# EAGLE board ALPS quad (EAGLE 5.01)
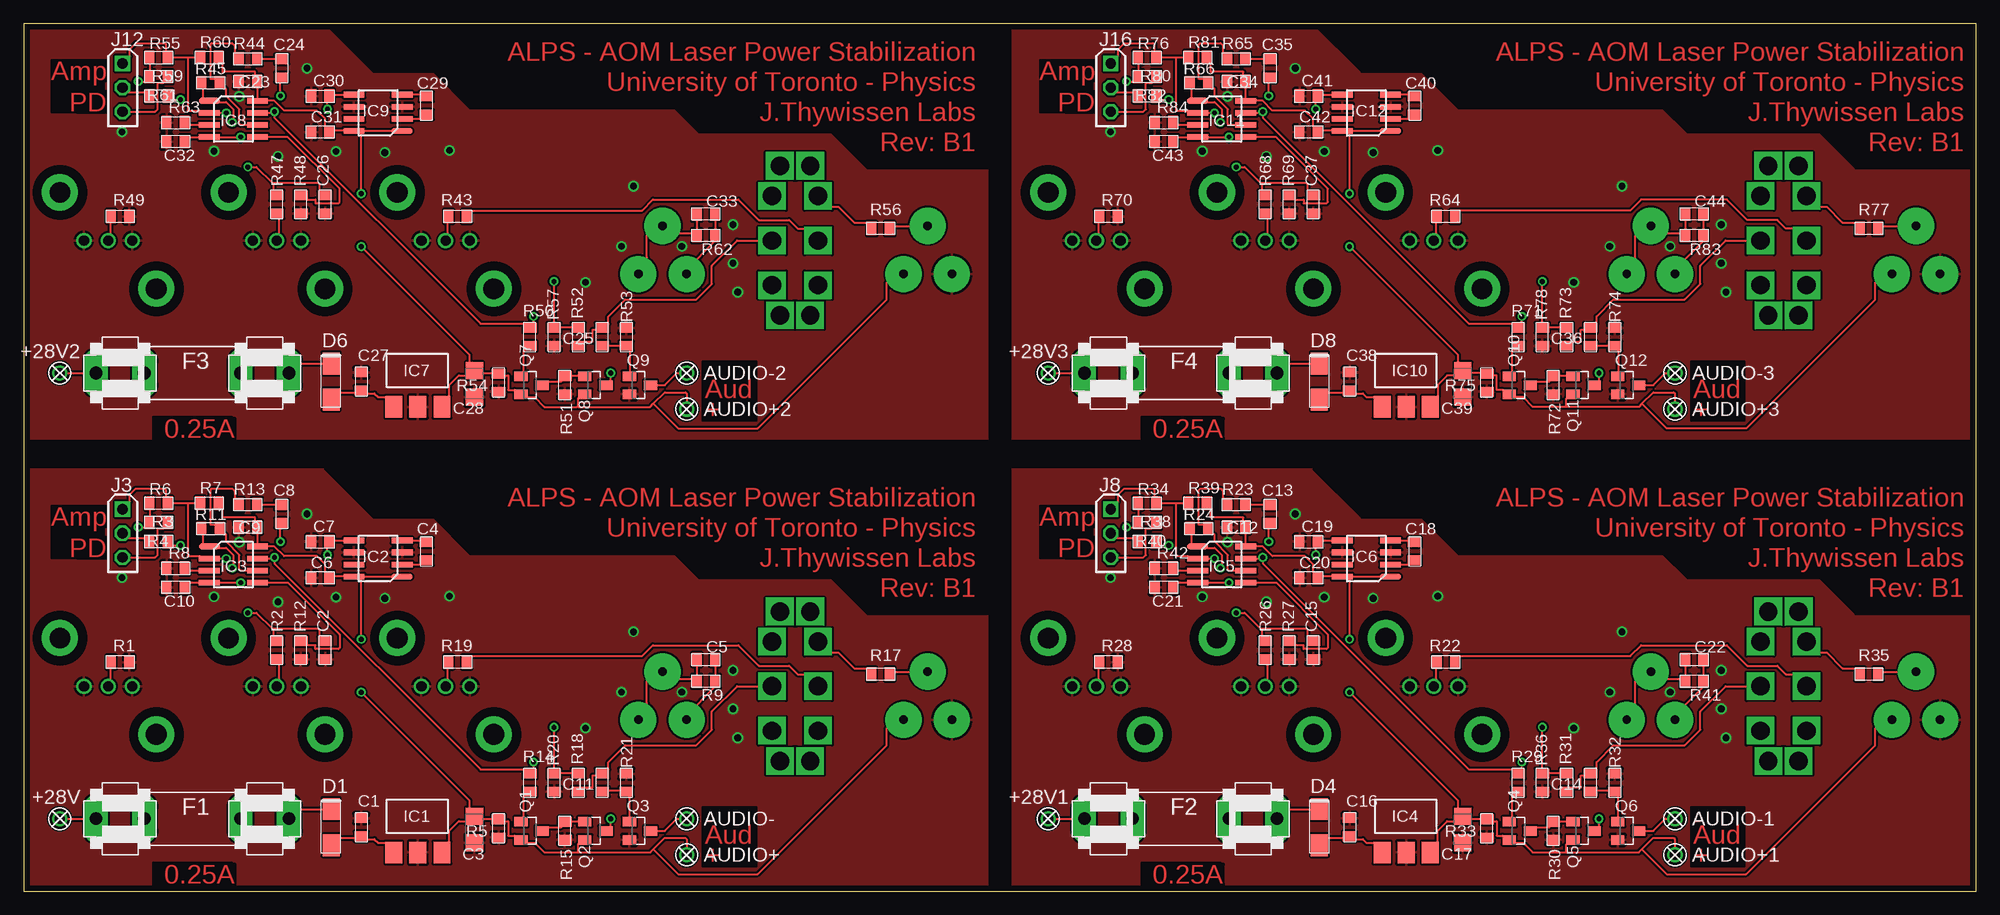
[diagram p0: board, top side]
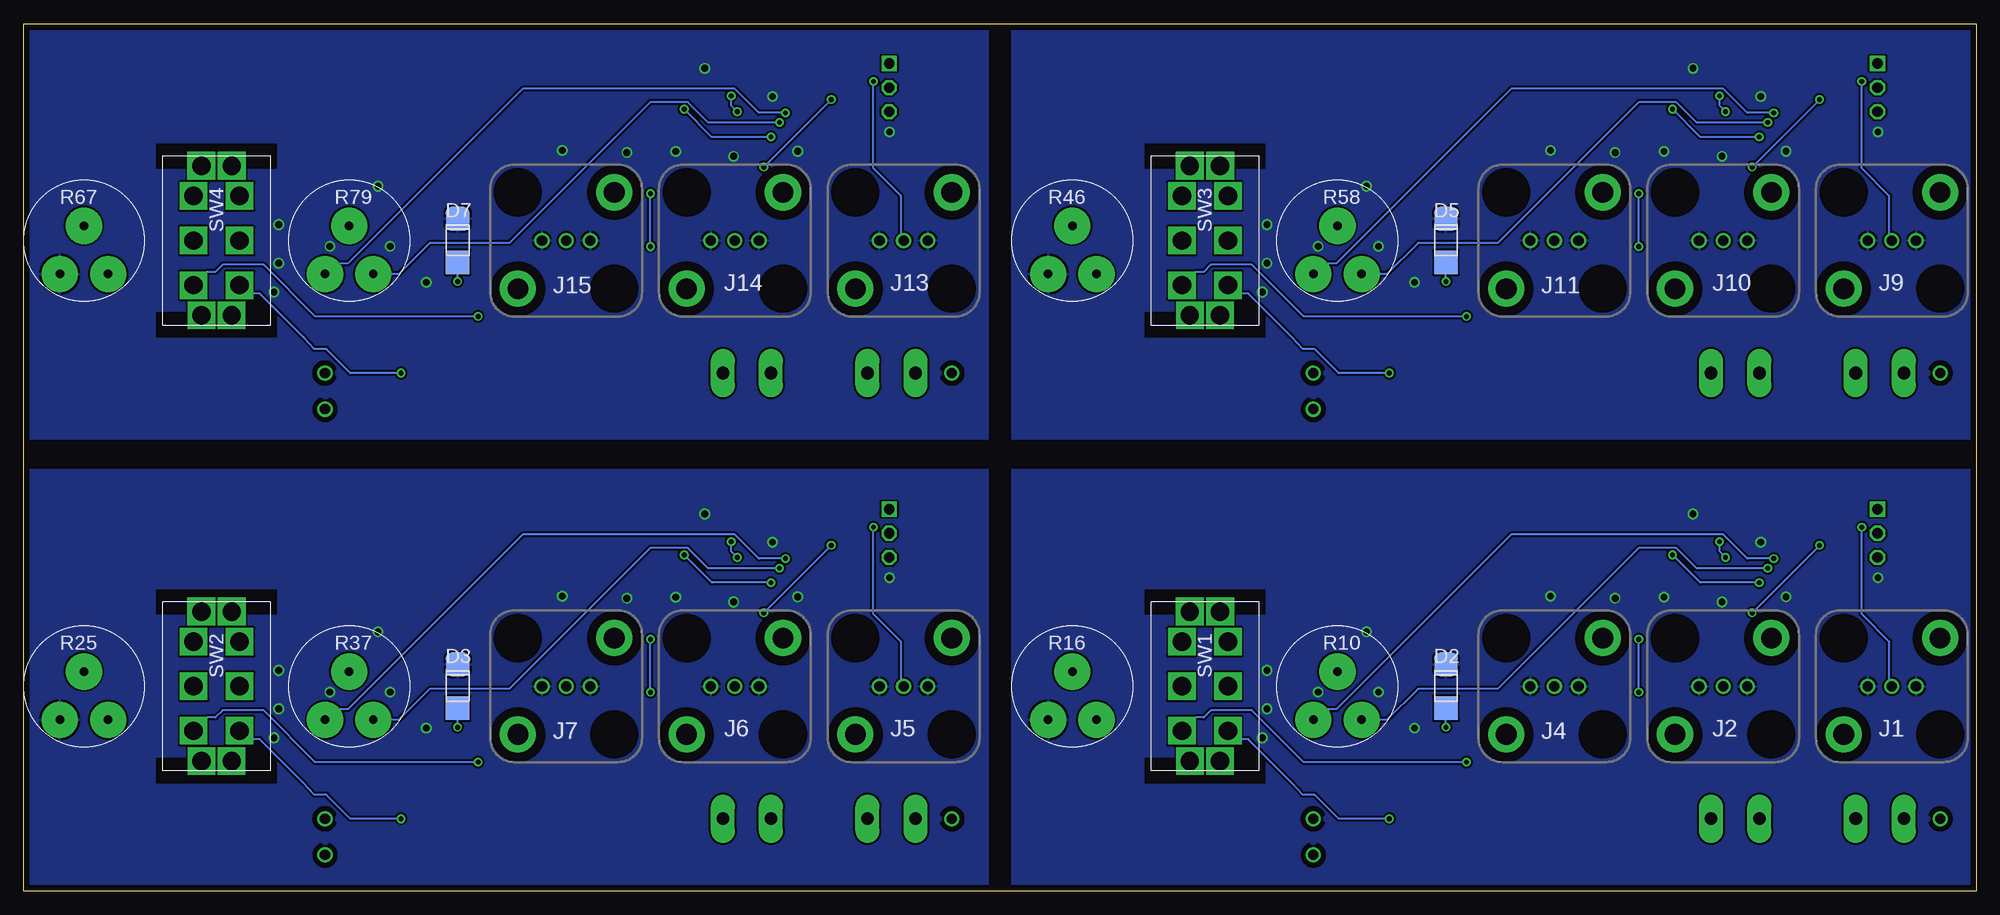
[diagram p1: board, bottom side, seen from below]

Size 205.74 x 91.44 mm. Coordinates in mm from the lower left corner, seen from the top.
Outline: 0,0 205.74,0 205.74,91.44 0,91.44 0,0
Copper layers (1*16): Top 0.035mm / dielectric 1.5mm / Bottom 0.035mm
Design rules "DRC standard check (8mil trace and gap, 20mil drill, etc)": minimum track width 7mil, minimum drill 20mil, track to track 7mil, track to pad 7mil, pad to pad 7mil, via to via 7mil, smd to smd 7mil, copper to edge 25mil, drill to drill 8mil, minimum pad ring 10mil, minimum via ring 8mil, stop-mask expansion 4mil, vias tented up to drill 0mil, thermal gap 10mil
Net classes: 0 default: width 0.203 mm, clearance 0.203 mm
tRestrict: 77 lines
bRestrict: 1 lines

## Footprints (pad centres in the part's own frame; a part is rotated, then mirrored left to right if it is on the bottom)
TP-0.042B = drill 1.067 round: TP 0,0
2012(0805) = smd 1.016 x 1.397: 1 -0.953,0; 2 0.953,0
3216(1206) = smd 1.8 x 1.8: 1 -1.4,0; 2 1.4,0
EIA-A(SMA) = smd 2.3 x 1.8: 1A -1.905,0; 2K 1.905,0
1209 = smd 2.5 x 2.5: A 2.3,0; K -2.3,0
FUSE = drill 1.321 pad 2.54 long: 1A -10.16,0; 1B -5.08,0; 2A 10.16,0; 2B 5.08,0
SOT223 = smd 1.778 x 2.286: 1 -2.54,-2.54; 2@1 0,-2.54; 3 2.54,-2.54
SOIC-8 = smd 0.6 x 2.2: 1 -1.27,-2.54; 2 0,-2.54; 3 1.27,-2.54; 4 2.54,-2.54; 5 2.54,2.54; 6 1.27,2.54; 7 0,2.54; 8 -1.27,2.54
CONN-BNC-AMP-TYPE1VERT = drill 1.067 round: CONDUCTOR 0,0; SHIELD1 -2.54,0; SHIELD2 2.54,0 | drill 2.184 pad 3.81 round: MTG1 -5.08,-5.08; MTG2 5.08,5.08
JUMPER-3 = drill 1.067 square: 1 0,2.54 | drill 1.067 octagon: 2 0,0; 3 0,-2.54
SOT23 = smd 1 x 1.4: 1 -0.953,-0.953; 2 0.953,-0.953; 3 0,1.27
PRECISION-SPR-RV8(POT) = drill 0.889 pad 3.81 round: CCW -2.54,-3.531; CW 2.54,-3.531; W 0,1.549
SWITCH-ESWITCH_100DP?VS2 = drill 1.93 square: C1 -2.42,0; C2 2.42,0; MTG3 1.595,-7.875; MTG4 -1.595,-7.875; NC1 -2.42,-4.7; NC2 2.42,-4.7; NO1 -2.42,4.7; NO2 2.42,4.7 | drill 1.93 pad 2.946 square: MTG1 -1.595,7.875; MTG2 1.595,7.875

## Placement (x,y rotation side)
+28V  Keystone 5002  [TP-0.042B]  3.81,7.62 180 top
+28V1  Keystone 5002  [TP-0.042B]  107.95,7.62 180 top
+28V2  Keystone 5002  [TP-0.042B]  3.81,54.61 180 top
+28V3  Keystone 5002  [TP-0.042B]  107.95,54.61 180 top
AUD  "Unlocked"  [MISC]  not placed on the board
AUDIO+  Keystone 5002  [TP-0.042B]  69.85,3.81 270 top
AUDIO+1  Keystone 5002  [TP-0.042B]  173.99,3.81 270 top
AUDIO+2  Keystone 5002  [TP-0.042B]  69.85,50.8 270 top
AUDIO+3  Keystone 5002  [TP-0.042B]  173.99,50.8 270 top
AUDIO-  Keystone 5002  [TP-0.042B]  69.85,7.62 0 top
AUDIO-1  Keystone 5002  [TP-0.042B]  173.99,7.62 0 top
AUDIO-2  Keystone 5002  [TP-0.042B]  69.85,54.61 0 top
AUDIO-3  Keystone 5002  [TP-0.042B]  173.99,54.61 0 top
C1  0.1uF  [2012(0805)]  35.56,6.73 270 top
C2  6.36nF???  [2012(0805)]  31.75,25.4 90 top
C3  10uF  [3216(1206)]  47.5,6.48 90 top
C4  10uF  [2012(0805)]  42.42,35.81 270 top
C5  10pF  [2012(0805)]  71.88,24.38 180 top
C6  0.1uF  [2012(0805)]  31.24,33.02 180 top
C7  10uF  [2012(0805)]  31.24,36.83 0 top
C8  100pF  [2012(0805)]  27.18,39.75 270 top
C9  0.1uF  [2012(0805)]  23.62,38.35 180 top
C10  0.1uF  [2012(0805)]  16,32 180 top
C11  3.3uF  [2012(0805)]  60.96,11.43 90 top
C12  0.1uF  [2012(0805)]  127.76,38.35 180 top
C13  100pF  [2012(0805)]  131.32,39.75 270 top
C14  3.3uF  [2012(0805)]  165.1,11.43 90 top
C15  6.36nF???  [2012(0805)]  135.89,25.4 90 top
C16  0.1uF  [2012(0805)]  139.7,6.73 270 top
C17  10uF  [3216(1206)]  151.64,6.48 90 top
C18  10uF  [2012(0805)]  146.56,35.81 270 top
C19  10uF  [2012(0805)]  135.38,36.83 0 top
C20  0.1uF  [2012(0805)]  135.38,33.02 180 top
C21  0.1uF  [2012(0805)]  120.14,32 180 top
C22  10pF  [2012(0805)]  176.02,24.38 180 top
C23  0.1uF  [2012(0805)]  23.62,85.34 180 top
C24  100pF  [2012(0805)]  27.18,86.74 270 top
C25  3.3uF  [2012(0805)]  60.96,58.42 90 top
C26  6.36nF???  [2012(0805)]  31.75,72.39 90 top
C27  0.1uF  [2012(0805)]  35.56,53.72 270 top
C28  10uF  [3216(1206)]  47.5,53.47 90 top
C29  10uF  [2012(0805)]  42.42,82.8 270 top
C30  10uF  [2012(0805)]  31.24,83.82 0 top
C31  0.1uF  [2012(0805)]  31.24,80.01 180 top
C32  0.1uF  [2012(0805)]  16,78.99 180 top
C33  10pF  [2012(0805)]  71.88,71.37 180 top
C34  0.1uF  [2012(0805)]  127.76,85.34 180 top
C35  100pF  [2012(0805)]  131.32,86.74 270 top
C36  3.3uF  [2012(0805)]  165.1,58.42 90 top
C37  6.36nF???  [2012(0805)]  135.89,72.39 90 top
C38  0.1uF  [2012(0805)]  139.7,53.72 270 top
C39  10uF  [3216(1206)]  151.64,53.47 90 top
C40  10uF  [2012(0805)]  146.56,82.8 270 top
C41  10uF  [2012(0805)]  135.38,83.82 0 top
C42  0.1uF  [2012(0805)]  135.38,80.01 180 top
C43  0.1uF  [2012(0805)]  120.14,78.99 180 top
C44  10pF  [2012(0805)]  176.02,71.37 180 top
CASE1  1590CFL  [MISC]  not placed on the board
D1  SMAZ16-13-F  [EIA-A(SMA)]  32.38,6.73 90 top
D2  Red  [1209]  55.88,21.59 270 bottom
D3  Red  [1209]  160.02,21.59 270 bottom
D4  SMAZ16-13-F  [EIA-A(SMA)]  136.53,6.73 90 top
D5  Red  [1209]  55.88,68.58 270 bottom
D6  SMAZ16-13-F  [EIA-A(SMA)]  32.38,53.72 90 top
D7  Red  [1209]  160.02,68.58 270 bottom
D8  SMAZ16-13-F  [EIA-A(SMA)]  136.53,53.72 90 top
F1  0.25A  [FUSE]  17.78,7.62 0 top
F2  0.25A  [FUSE]  121.92,7.62 0 top
F3  0.25A  [FUSE]  17.78,54.61 0 top
F4  0.25A  [FUSE]  121.92,54.61 0 top
IC1  MIC2920A-5.0WS  [SOT223]  41.53,6.6 0 top
IC2  LM2662M  [SOIC-8]  37.34,34.42 90 top
IC3  AD8032AR(z)  [SOIC-8]  22.1,35.05 270 top
IC4  MIC2920A-5.0WS  [SOT223]  145.67,6.6 0 top
IC5  AD8032AR(z)  [SOIC-8]  126.24,35.05 270 top
IC6  LM2662M  [SOIC-8]  141.48,34.42 90 top
IC7  MIC2920A-5.0WS  [SOT223]  41.53,53.59 0 top
IC8  AD8032AR(z)  [SOIC-8]  22.1,82.04 270 top
IC9  LM2662M  [SOIC-8]  37.34,81.41 90 top
IC10  MIC2920A-5.0WS  [SOT223]  145.67,53.59 0 top
IC11  AD8032AR(z)  [SOIC-8]  126.24,82.04 270 top
IC12  LM2662M  [SOIC-8]  141.48,81.41 90 top
J1  5227222-6  [CONN-BNC-AMP-TYPE1VERT]  8.89,21.59 0 bottom
J2  5227222-6  [CONN-BNC-AMP-TYPE1VERT]  26.67,21.59 0 bottom
J3  [JUMPER-3]  10.41,37.72 0 top
J4  5227222-6  [CONN-BNC-AMP-TYPE1VERT]  44.45,21.59 0 bottom
J5  5227222-6  [CONN-BNC-AMP-TYPE1VERT]  113.03,21.59 0 bottom
J6  5227222-6  [CONN-BNC-AMP-TYPE1VERT]  130.81,21.59 0 bottom
J7  5227222-6  [CONN-BNC-AMP-TYPE1VERT]  148.59,21.59 0 bottom
J8  [JUMPER-3]  114.55,37.72 0 top
J9  5227222-6  [CONN-BNC-AMP-TYPE1VERT]  8.89,68.58 0 bottom
J10  5227222-6  [CONN-BNC-AMP-TYPE1VERT]  26.67,68.58 0 bottom
J11  5227222-6  [CONN-BNC-AMP-TYPE1VERT]  44.45,68.58 0 bottom
J12  [JUMPER-3]  10.41,84.71 0 top
J13  5227222-6  [CONN-BNC-AMP-TYPE1VERT]  113.03,68.58 0 bottom
J14  5227222-6  [CONN-BNC-AMP-TYPE1VERT]  130.81,68.58 0 bottom
J15  5227222-6  [CONN-BNC-AMP-TYPE1VERT]  148.59,68.58 0 bottom
J16  [JUMPER-3]  114.55,84.71 0 top
KNOB1  OESA-50-4-6  [MISC]  not placed on the board
KNOB2  OESA-50-4-6  [MISC]  not placed on the board
LIGHTPIPE1  PLP2-500  [MISC]  not placed on the board
NUT1  1-329631-2  [MISC]  not placed on the board
NUT2  1-329631-2  [MISC]  not placed on the board
NUT3  1-329631-2  [MISC]  not placed on the board
Q1  MMBT3906  [SOT23]  53.34,6.35 270 top
Q2  MMBT3906  [SOT23]  60.07,6.35 270 top
Q3  2N7002TA  [SOT23]  64.77,6.35 270 top
Q4  MMBT3906  [SOT23]  157.48,6.35 270 top
Q5  MMBT3906  [SOT23]  164.21,6.35 270 top
Q6  2N7002TA  [SOT23]  168.91,6.35 270 top
Q7  MMBT3906  [SOT23]  53.34,53.34 270 top
Q8  MMBT3906  [SOT23]  60.07,53.34 270 top
Q9  2N7002TA  [SOT23]  64.77,53.34 270 top
Q10  MMBT3906  [SOT23]  157.48,53.34 270 top
Q11  MMBT3906  [SOT23]  164.21,53.34 270 top
Q12  2N7002TA  [SOT23]  168.91,53.34 270 top
R1  66.5  [2012(0805)]  10.16,24.13 180 top
R2  402  [2012(0805)]  26.67,25.4 90 top
R3  9.31K  [2012(0805)]  14.22,38.86 180 top
R4  402  [2012(0805)]  14.22,36.83 180 top
R5  2.49K  [2012(0805)]  50.04,6.6 90 top
R6  200  [2012(0805)]  14.22,40.89 0 top
R7  Out  [2012(0805)]  19.56,40.89 0 top
R8  402  [2012(0805)]  16,34.04 0 top
R9  10K  [2012(0805)]  71.88,22.1 180 top
R10  1K  [PRECISION-SPR-RV8(POT)]  67.31,21.59 0 bottom
R11  1.5K  [2012(0805)]  19.68,38.23 0 top
R12  1.5K  [2012(0805)]  29.21,25.4 90 top
R13  10K  [2012(0805)]  23.62,40.77 0 top
R14  10K  [2012(0805)]  53.34,11.43 90 top
R15  10K  [2012(0805)]  57.02,6.35 90 top
R16  1K  [PRECISION-SPR-RV8(POT)]  95.25,21.59 0 bottom
R17  49.9  [2012(0805)]  90.3,22.86 180 top
R18  1K  [2012(0805)]  58.42,11.43 270 top
R19  158  [2012(0805)]  45.72,24.13 180 top
R20  10K  [2012(0805)]  55.88,11.43 90 top
R21  1M  [2012(0805)]  63.5,11.43 270 top
R22  158  [2012(0805)]  149.86,24.13 180 top
R23  10K  [2012(0805)]  127.76,40.77 0 top
R24  1.5K  [2012(0805)]  123.83,38.23 0 top
R25  1K  [PRECISION-SPR-RV8(POT)]  199.39,21.59 0 bottom
R26  402  [2012(0805)]  130.81,25.4 90 top
R27  1.5K  [2012(0805)]  133.35,25.4 90 top
R28  66.5  [2012(0805)]  114.3,24.13 180 top
R29  10K  [2012(0805)]  157.48,11.43 90 top
R30  10K  [2012(0805)]  161.16,6.35 90 top
R31  1K  [2012(0805)]  162.56,11.43 270 top
R32  1M  [2012(0805)]  167.64,11.43 270 top
R33  2.49K  [2012(0805)]  154.18,6.6 90 top
R34  200  [2012(0805)]  118.36,40.89 0 top
R35  49.9  [2012(0805)]  194.44,22.86 180 top
R36  10K  [2012(0805)]  160.02,11.43 90 top
R37  1K  [PRECISION-SPR-RV8(POT)]  171.45,21.59 0 bottom
R38  9.31K  [2012(0805)]  118.36,38.86 180 top
R39  Out  [2012(0805)]  123.7,40.89 0 top
R40  402  [2012(0805)]  118.36,36.83 180 top
R41  10K  [2012(0805)]  176.02,22.1 180 top
R42  402  [2012(0805)]  120.14,34.04 0 top
R43  158  [2012(0805)]  45.72,71.12 180 top
R44  10K  [2012(0805)]  23.62,87.76 0 top
R45  1.5K  [2012(0805)]  19.68,85.22 0 top
R46  1K  [PRECISION-SPR-RV8(POT)]  95.25,68.58 0 bottom
R47  402  [2012(0805)]  26.67,72.39 90 top
R48  1.5K  [2012(0805)]  29.21,72.39 90 top
R49  66.5  [2012(0805)]  10.16,71.12 180 top
R50  10K  [2012(0805)]  53.34,58.42 90 top
R51  10K  [2012(0805)]  57.02,53.34 90 top
R52  1K  [2012(0805)]  58.42,58.42 270 top
R53  1M  [2012(0805)]  63.5,58.42 270 top
R54  2.49K  [2012(0805)]  50.04,53.59 90 top
R55  200  [2012(0805)]  14.22,87.88 0 top
R56  49.9  [2012(0805)]  90.3,69.85 180 top
R57  10K  [2012(0805)]  55.88,58.42 90 top
R58  1K  [PRECISION-SPR-RV8(POT)]  67.31,68.58 0 bottom
R59  9.31K  [2012(0805)]  14.22,85.85 180 top
R60  Out  [2012(0805)]  19.56,87.88 0 top
R61  402  [2012(0805)]  14.22,83.82 180 top
R62  10K  [2012(0805)]  71.88,69.09 180 top
R63  402  [2012(0805)]  16,81.03 0 top
R64  158  [2012(0805)]  149.86,71.12 180 top
R65  10K  [2012(0805)]  127.76,87.76 0 top
R66  1.5K  [2012(0805)]  123.83,85.22 0 top
R67  1K  [PRECISION-SPR-RV8(POT)]  199.39,68.58 0 bottom
R68  402  [2012(0805)]  130.81,72.39 90 top
R69  1.5K  [2012(0805)]  133.35,72.39 90 top
R70  66.5  [2012(0805)]  114.3,71.12 180 top
R71  10K  [2012(0805)]  157.48,58.42 90 top
R72  10K  [2012(0805)]  161.16,53.34 90 top
R73  1K  [2012(0805)]  162.56,58.42 270 top
R74  1M  [2012(0805)]  167.64,58.42 270 top
R75  2.49K  [2012(0805)]  154.18,53.59 90 top
R76  200  [2012(0805)]  118.36,87.88 0 top
R77  49.9  [2012(0805)]  194.44,69.85 180 top
R78  10K  [2012(0805)]  160.02,58.42 90 top
R79  1K  [PRECISION-SPR-RV8(POT)]  171.45,68.58 0 bottom
R80  9.31K  [2012(0805)]  118.36,85.85 180 top
R81  Out  [2012(0805)]  123.7,87.88 0 top
R82  402  [2012(0805)]  118.36,83.82 180 top
R83  10K  [2012(0805)]  176.02,69.09 180 top
R84  402  [2012(0805)]  120.14,81.03 0 top
SW1  100DP3T2B4VS2RE  [SWITCH-ESWITCH_100DP?VS2]  81.28,21.59 0 bottom
SW2  100DP3T2B4VS2RE  [SWITCH-ESWITCH_100DP?VS2]  185.42,21.59 0 bottom
SW3  100DP3T2B4VS2RE  [SWITCH-ESWITCH_100DP?VS2]  81.28,68.58 0 bottom
SW4  100DP3T2B4VS2RE  [SWITCH-ESWITCH_100DP?VS2]  185.42,68.58 0 bottom
U$18  [TITLEBLOCK_PCB]  not placed on the board
WASH1  1-329632-2  [MISC]  not placed on the board
WASH2  1-329632-2  [MISC]  not placed on the board
WASH3  1-329632-2  [MISC]  not placed on the board

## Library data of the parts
+28V +28V1-+28V3 AUDIO+ AUDIO+1-AUDIO+3 AUDIO- AUDIO-1-AUDIO-3 C1 C2 C5 C6 C8-C10 C12 C13 C15 C16 C20-C24 C26 C27 C31-C35 C37 C38 C42-C44 IC2 IC3 IC5 IC6 IC8 IC9 IC11 IC12 Q1 Q2 Q4 Q5 Q7 Q8 Q10 Q11 R1-R9 R11-R15 R17-R24 R26-R36 R38-R45 R47-R57 R59-R66 R68-R78 R80-R84 U$18 WASH1-WASH3 = QuantumOptics
AUD = QuantumOptics; MFG: Mallory; PN: MSR516WR
C3 C17 C28 C39 = QuantumOptics; MFG: Nichicon; PN: F951C106MSAAQ2
C4 C7 C18 C19 C29 C30 C40 C41 = QuantumOptics; DESC: Low ESR; MFG: AVX; PN: TCJR106M006R0500
C11 C14 C25 C36 = QuantumOptics; MFG: Yageo; PN: CC0805ZKY5V6BB335
CASE1 = QuantumOptics; MFG: Hammond
D1 D4 D6 D8 = QuantumOptics; MFG: Diodes Inc; RATING: 10V/1W
D2 D3 D5 D7 = QuantumOptics; DESC: "Unlocked"; MFG: Lumex; PN: SML-LXL1209SIC
F1-F4 = QuantumOptics; MFG: Littlefuse; PN: 100056
IC1 IC4 IC7 IC10 = QuantumOptics; MFG: Micrel
J1 J5 J9 J13 = QuantumOptics; DESC: "PD In"; MFG: Amp
J2 J4 J6 J7 J10 J11 J14 J15 = QuantumOptics; DESC: "PD Input"; MFG: Amp
J3 J8 J12 J16 = QuantumOptics; POS1: Amplif.; POS2: PD
KNOB1 KNOB2 = QuantumOptics; MFG: Kilo Int'l
LIGHTPIPE1 = QuantumOptics; MFG: Bivar inc.
NUT1-NUT3 = QuantumOptics; MFG: Amp
Q3 Q6 Q9 Q12 = QuantumOptics; MFG: Zetex; PKG: SOT23
R10 R37 R58 R79 = QuantumOptics; DESC: "Gain"; MFG: Precision Electronics Components; PN: SPRU1031S28
R16 R25 R46 R67 = QuantumOptics; MFG: Precision Electronics Components; PN: SPRU1021S28
SW1-SW4 = QuantumOptics; DESC: "Man/Auto"; MFG: E-Switch

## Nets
+5V: AUDIO+.TP C3.2 C6.1 C9.1 IC1.3 IC2.1 IC2.8 IC3.8 Q1.2 Q2.2 R5.2 R7.2 R16.CW
+5V1: AUDIO+1.TP C12.1 C17.2 C20.1 IC4.3 IC5.8 IC6.1 IC6.8 Q4.2 Q5.2 R25.CW R33.2 R39.2
+5V2: AUDIO+2.TP C23.1 C28.2 C31.1 IC7.3 IC8.8 IC9.1 IC9.8 Q7.2 Q8.2 R46.CW R54.2 R60.2
+5V3: AUDIO+3.TP C34.1 C39.2 C42.1 IC10.3 IC11.8 IC12.1 IC12.8 Q10.2 Q11.2 R67.CW R75.2 R81.2
-5V: C7.2 C10.1 IC2.5 IC3.4
-5V1: C19.2 C21.1 IC5.4 IC6.5
-5V2: C30.2 C32.1 IC8.4 IC9.5
-5V3: C41.2 C43.1 IC11.4 IC12.5
AGND: C1.1 C2.1 C3.1 C6.2 C7.1 C9.2 C10.2 D2.K IC1.2@1 IC2.3 IC2.6 J1.SHIELD1 J1.SHIELD2 J2.SHIELD1 J2.SHIELD2 J4.SHIELD1 J4.SHIELD2 Q3.2 R1.1 R5.1 R8.1 R12.1 R15.1 R16.CCW R20.1 R21.1
AGND1: C12.2 C15.1 C16.1 C17.1 C19.1 C20.2 C21.2 D3.K IC4.2@1 IC6.3 IC6.6 J5.SHIELD1 J5.SHIELD2 J6.SHIELD1 J6.SHIELD2 J7.SHIELD1 J7.SHIELD2 Q6.2 R25.CCW R27.1 R28.1 R30.1 R32.1 R33.1 R36.1 R42.1
AGND2: C23.2 C26.1 C27.1 C28.1 C30.1 C31.2 C32.2 D5.K IC7.2@1 IC9.3 IC9.6 J9.SHIELD1 J9.SHIELD2 J10.SHIELD1 J10.SHIELD2 J11.SHIELD1 J11.SHIELD2 Q9.2 R46.CCW R48.1 R49.1 R51.1 R53.1 R54.1 R57.1 R63.1
AGND3: C34.2 C37.1 C38.1 C39.1 C41.1 C42.2 C43.2 D7.K IC10.2@1 IC12.3 IC12.6 J13.SHIELD1 J13.SHIELD2 J14.SHIELD1 J14.SHIELD2 J15.SHIELD1 J15.SHIELD2 Q12.2 R67.CCW R69.1 R70.1 R72.1 R74.1 R75.1 R78.1 R84.1
N$1: J4.CONDUCTOR R19.2
N$2: C8.2 IC3.7 R14.2 SW1.NC1
N$3: IC3.6 R11.2 R13.1
N$4: C8.1 R13.2
N$5: R19.1 SW1.C1
N$6: R17.2 SW1.NO1
N$7: J2.CONDUCTOR R2.1
N$8: IC3.5 R12.2
N$9: Q1.3 Q2.1 R15.2
N$10: J1.CONDUCTOR R1.2 R3.2 R6.1
N$11: Q1.1 R14.1
N$12: C11.2 R18.2 SW1.C2
N$13: D2.A R18.1 R20.2
N$14: Q2.3 SW1.NC2
N$15: C11.1 Q3.1 R21.2
N$16: AUDIO-.TP Q3.3
N$17: C1.2 D1.1A IC1.1
N$18: C4.2 IC2.2
N$19: +28V.TP F1.1A
N$20: D1.2K F1.2A
N$21: C5.2 IC3.1 R9.2 R10.CW R10.W R11.1
N$22: C5.1 IC3.2 J3.1 R6.2 R7.1 R9.1 R10.CCW
N$23: J3.2 R4.2
N$24: R16.W R17.1
N$25: IC3.3 R8.2
N$26: C4.1 IC2.4
N$27: C2.2 R2.2 R4.1
N$28: J7.CONDUCTOR R22.2
N$29: J3.3 R3.1
N$30: C13.2 IC5.7 R29.2 SW2.NC1
N$31: IC5.6 R23.1 R24.2
N$32: C13.1 R23.2
N$33: R22.1 SW2.C1
N$34: R35.2 SW2.NO1
N$35: J6.CONDUCTOR R26.1
N$36: IC5.5 R27.2
N$37: J5.CONDUCTOR R28.2 R34.1 R38.2
N$38: Q4.3 Q5.1 R30.2
N$39: Q4.1 R29.1
N$40: C14.2 R31.2 SW2.C2
N$41: D3.A R31.1 R36.2
N$42: C14.1 Q6.1 R32.2
N$43: C16.2 D4.1A IC4.1
N$44: D4.2K F2.2A
N$45: +28V1.TP F2.1A
N$46: R25.W R35.1
N$47: Q5.3 SW2.NC2
N$48: AUDIO-1.TP Q6.3
N$49: C18.2 IC6.2
N$50: C18.1 IC6.4
N$51: C15.2 R26.2 R40.1
N$52: C22.2 IC5.1 R24.1 R37.CW R37.W R41.2
N$53: C22.1 IC5.2 J8.1 R34.2 R37.CCW R39.1 R41.1
N$54: J8.2 R40.2
N$55: J8.3 R38.1
N$56: IC5.3 R42.2
N$57: J11.CONDUCTOR R43.2
N$58: C24.2 IC8.7 R50.2 SW3.NC1
N$59: IC8.6 R44.1 R45.2
N$60: C24.1 R44.2
N$61: R43.1 SW3.C1
N$62: R56.2 SW3.NO1
N$63: J10.CONDUCTOR R47.1
N$64: IC8.5 R48.2
N$65: J9.CONDUCTOR R49.2 R55.1 R59.2
N$66: Q7.3 Q8.1 R51.2
N$67: Q7.1 R50.1
N$68: C25.2 R52.2 SW3.C2
N$69: D5.A R52.1 R57.2
N$70: C25.1 Q9.1 R53.2
N$71: C27.2 D6.1A IC7.1
N$72: D6.2K F3.2A
N$73: +28V2.TP F3.1A
N$74: R46.W R56.1
N$75: Q8.3 SW3.NC2
N$76: AUDIO-2.TP Q9.3
N$77: C29.2 IC9.2
N$78: C29.1 IC9.4
N$79: C26.2 R47.2 R61.1
N$80: C33.2 IC8.1 R45.1 R58.CW R58.W R62.2
N$81: C33.1 IC8.2 J12.1 R55.2 R58.CCW R60.1 R62.1
N$82: J12.2 R61.2
N$83: J12.3 R59.1
N$84: IC8.3 R63.2
N$85: J15.CONDUCTOR R64.2
N$86: C35.2 IC11.7 R71.2 SW4.NC1
N$87: IC11.6 R65.1 R66.2
N$88: C35.1 R65.2
N$89: R64.1 SW4.C1
N$90: R77.2 SW4.NO1
N$91: J14.CONDUCTOR R68.1
N$92: IC11.5 R69.2
N$93: J13.CONDUCTOR R70.2 R76.1 R80.2
N$94: Q10.3 Q11.1 R72.2
N$95: Q10.1 R71.1
N$96: C36.2 R73.2 SW4.C2
N$97: D7.A R73.1 R78.2
N$98: C36.1 Q12.1 R74.2
N$99: C38.2 D8.1A IC10.1
N$100: D8.2K F4.2A
N$101: +28V3.TP F4.1A
N$102: R67.W R77.1
N$103: Q11.3 SW4.NC2
N$104: AUDIO-3.TP Q12.3
N$105: C40.2 IC12.2
N$106: C40.1 IC12.4
N$107: C37.2 R68.2 R82.1
N$108: C44.2 IC11.1 R66.1 R79.CW R79.W R83.2
N$109: C44.1 IC11.2 J16.1 R76.2 R79.CCW R81.1 R83.1
N$110: J16.2 R82.2
N$111: J16.3 R80.1
N$112: IC11.3 R84.2

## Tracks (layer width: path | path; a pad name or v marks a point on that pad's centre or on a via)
+5V  (via drill 0.51)
  Top 0.203: IC2.8 32.64,33.15 C6.1 31.75,33.66 31.75,34.42 30.86,35.31 27.43,35.31 26.42,36.32 IC3.8 24.64,37.72 C9.1 24.38,38.99 24.38,39.37 20.95,39.37 20.95,40.26 R7.2 | IC2.8 IC2.1 | C3.2 48.39,7.62 49.4,7.62 R5.2 50.67,7.37 51.05,7.37 51.05,5.84 51.69,5.84 Q1.2 53.09,5.08 53.85,5.08 54.86,4.06 58.29,4.06 58.36,4.13 | 58.36,4.13 58.42,4.19 58.42,4.95 Q2.2 | IC1.3 44.83,5.08 44.83,6.35 45.85,7.37 46.61,7.37 C3.2 | 66.36,4.38 66.04,4.06 58.42,4.06 58.36,4.13 | 66.36,4.38 67.56,5.59 69.72,5.59 69.85,5.46 AUDIO+.TP | R16.CW 90.93,17.14 90.93,15.37 77.34,1.78 68.96,1.78 66.36,4.38 | v35.56,26.54 35.56,32.89 IC2.8 | v35.56,20.95 46.99,9.53 46.99,8.76 C3.2
  Bottom 0.203: v35.56,20.95 v35.56,26.54
+5V1  (via drill 0.51)
  Top 0.203: IC6.8 136.78,33.15 C20.1 135.89,33.66 135.89,34.42 135,35.31 131.57,35.31 130.56,36.32 IC5.8 128.78,37.72 C12.1 128.52,38.99 128.52,39.37 125.09,39.37 125.09,40.26 R39.2 | IC6.8 IC6.1 | C17.2 152.53,7.62 153.54,7.62 R33.2 154.81,7.37 155.19,7.37 155.19,5.84 155.83,5.84 Q4.2 157.23,5.08 157.99,5.08 159,4.06 162.43,4.06 162.5,4.13 | 162.5,4.13 162.56,4.19 162.56,4.95 Q5.2 | IC4.3 148.97,5.08 148.97,6.35 149.99,7.37 150.75,7.37 C17.2 | 170.5,4.38 170.18,4.06 162.56,4.06 162.5,4.13 | 170.5,4.38 171.7,5.59 173.86,5.59 173.99,5.46 AUDIO+1.TP | R25.CW 195.07,17.14 195.07,15.37 181.48,1.78 173.1,1.78 170.5,4.38 | v139.7,26.54 139.7,32.89 IC6.8 | v139.7,20.95 151.13,9.53 151.13,8.76 C17.2
  Bottom 0.203: v139.7,20.95 v139.7,26.54
+5V2  (via drill 0.51)
  Top 0.203: IC9.8 32.64,80.14 C31.1 31.75,80.64 31.75,81.41 30.86,82.3 27.43,82.3 26.42,83.31 IC8.8 24.64,84.71 C23.1 24.38,85.98 24.38,86.36 20.95,86.36 20.95,87.25 R60.2 | IC9.8 IC9.1 | C28.2 48.39,54.61 49.4,54.61 R54.2 50.67,54.36 51.05,54.36 51.05,52.83 51.69,52.83 Q7.2 53.09,52.07 53.85,52.07 54.86,51.05 58.29,51.05 58.36,51.12 | 58.36,51.12 58.42,51.18 58.42,51.94 Q8.2 | IC7.3 44.83,52.07 44.83,53.34 45.85,54.36 46.61,54.36 C28.2 | 66.36,51.37 66.04,51.05 58.42,51.05 58.36,51.12 | 66.36,51.37 67.56,52.58 69.72,52.58 69.85,52.45 AUDIO+2.TP | R46.CW 90.93,64.14 90.93,62.36 77.34,48.77 68.96,48.77 66.36,51.37 | v35.56,73.53 35.56,79.88 IC9.8 | v35.56,67.94 46.99,56.52 46.99,55.75 C28.2
  Bottom 0.203: v35.56,67.94 v35.56,73.53
+5V3  (via drill 0.51)
  Top 0.203: IC12.8 136.78,80.14 C42.1 135.89,80.64 135.89,81.41 135,82.3 131.57,82.3 130.56,83.31 IC11.8 128.78,84.71 C34.1 128.52,85.98 128.52,86.36 125.09,86.36 125.09,87.25 R81.2 | IC12.8 IC12.1 | C39.2 152.53,54.61 153.54,54.61 R75.2 154.81,54.36 155.19,54.36 155.19,52.83 155.83,52.83 Q10.2 157.23,52.07 157.99,52.07 159,51.05 162.43,51.05 162.5,51.12 | 162.5,51.12 162.56,51.18 162.56,51.94 Q11.2 | IC10.3 148.97,52.07 148.97,53.34 149.99,54.36 150.75,54.36 C39.2 | 170.5,51.37 170.18,51.05 162.56,51.05 162.5,51.12 | 170.5,51.37 171.7,52.58 173.86,52.58 173.99,52.45 AUDIO+3.TP | R67.CW 195.07,64.14 195.07,62.36 181.48,48.77 173.1,48.77 170.5,51.37 | v139.7,73.53 139.7,79.88 IC12.8 | v139.7,67.94 151.13,56.52 151.13,55.75 C39.2
  Bottom 0.203: v139.7,67.94 v139.7,73.53
-5V  (via drill 0.51)
  Top 0.203: C10.1 17.4,32.51 IC3.4 v22.86,32.51 | IC2.5 32.64,36.96 C7.2 32,36.2 v32,35.43
  Bottom 0.203: v22.86,32.51 29.08,32.51 v32,35.43
-5V1  (via drill 0.51)
  Top 0.203: C21.1 121.54,32.51 IC5.4 v127,32.51 | IC6.5 136.78,36.96 C19.2 136.14,36.2 v136.14,35.43
  Bottom 0.203: v127,32.51 133.22,32.51 v136.14,35.43
-5V2  (via drill 0.51)
  Top 0.203: C32.1 17.4,79.5 IC8.4 v22.86,79.5 | IC9.5 32.64,83.95 C30.2 32,83.19 v32,82.42
  Bottom 0.203: v22.86,79.5 29.08,79.5 v32,82.42
-5V3  (via drill 0.51)
  Top 0.203: C43.1 121.54,79.5 IC11.4 v127,79.5 | IC12.5 136.78,83.95 C41.2 136.14,83.19 v136.14,82.42
  Bottom 0.203: v127,79.5 133.22,79.5 v136.14,82.42
AGND  (via drill 0.71)
  other vias: 29.84,39.75 32.89,30.99 26.8,30.48 22.71,36.78 20.04,31.01 10.36,33.05 38.05,30.86 44.86,31.09 69.34,20.98 74.73,23.27 74.73,19.2 75.23,16.15 62.99,20.98 59.18,17.17 64.26,27.33
  pour Top: 0,0 101.6,0 101.6,29.21 88.9,29.21 85.09,33.02 71.12,33.02 68.58,35.56 46.99,35.56 43.18,39.37 36.83,39.37 31.75,44.45 0,44.45
  pour Bottom: 0,0 101.6,0 101.6,44.45 0,44.45
AGND1  (via drill 0.71)
  other vias: 133.99,39.75 137.03,30.99 130.94,30.48 126.85,36.78 124.18,31.01 114.5,33.05 142.19,30.86 149,31.09 173.48,20.98 178.87,23.27 178.87,19.2 179.37,16.15 167.13,20.98 163.32,17.17 168.4,27.33
  pour Top: 104.14,0 205.74,0 205.74,29.21 193.04,29.21 189.23,33.02 175.26,33.02 172.72,35.56 151.13,35.56 147.32,39.37 140.97,39.37 135.89,44.45 104.14,44.45
  pour Bottom: 104.14,0 205.74,0 205.74,44.45 104.14,44.45
AGND2  (via drill 0.71)
  other vias: 29.84,86.74 32.89,77.98 26.8,77.47 22.71,83.77 20.04,78 10.36,80.04 38.05,77.85 44.86,78.08 69.34,67.97 74.73,70.26 74.73,66.19 75.23,63.14 62.99,67.97 59.18,64.16 64.26,74.32
  pour Top: 0,46.99 101.6,46.99 101.6,76.2 88.9,76.2 85.09,80.01 71.12,80.01 68.58,82.55 46.99,82.55 43.18,86.36 36.83,86.36 31.75,91.44 0,91.44
  pour Bottom: 0,46.99 101.6,46.99 101.6,91.44 0,91.44
AGND3  (via drill 0.71)
  other vias: 133.99,86.74 137.03,77.98 130.94,77.47 126.85,83.77 124.18,78 114.5,80.04 142.19,77.85 149,78.08 173.48,67.97 178.87,70.26 178.87,66.19 179.37,63.14 167.13,67.97 163.32,64.16 168.4,74.32
  pour Top: 104.14,46.99 205.74,46.99 205.74,76.2 193.04,76.2 189.23,80.01 175.26,80.01 172.72,82.55 151.13,82.55 147.32,86.36 140.97,86.36 135.89,91.44 104.14,91.44
  pour Bottom: 104.14,46.99 205.74,46.99 205.74,91.44 104.14,91.44
N$1
  Top 0.203: R19.2 44.7,23.5 44.7,22.35 J4.CONDUCTOR
N$2  (via drill 0.51)
  Top 0.203: 26.42,35.05 26.42,34.54 48.13,12.83 52.7,12.83 R14.2 53.72,12.83 v53.72,13.59 | IC3.7 26.42,35.05 | v27.05,36.83 27.05,38.35 C8.2 | 26.42,35.05 v26.42,35.18
  Bottom 0.203: v27.05,36.83 27.05,35.81 v26.42,35.18 | v53.72,13.59 70.87,13.59 76.33,19.05 80.64,19.05 81.41,18.29 82.3,18.29 SW1.NC1
N$3
  Top 0.203: IC3.6 22.86,33.78 22.73,33.91 22.73,35.43 21.34,36.83 21.34,37.59 21.08,37.59 R11.2 20.19,38.61 19.68,38.61 19.68,42.29 19.81,42.42 21.97,42.42 22.23,42.16 22.23,41.4 R13.1
N$4
  Top 0.203: R13.2 26.54,40.77 C8.1
N$5
  Top 0.203: R19.1 47.12,24.77 65.15,24.77 66.29,25.91 75.31,25.91 77.47,23.75 80.64,23.75 81.53,22.86 82.3,22.86 SW1.C1
N$6
  Top 0.203: R17.2 88.9,23.5 87.5,23.5 85.85,25.15 85.09,25.15 SW1.NO1
N$7
  Top 0.203: R2.1 26.92,24 26.92,22.35 J2.CONDUCTOR
N$8
  Top 0.203: R12.2 29.84,25.91 30.73,25.91 30.73,25.53 33.15,25.53 33.27,25.65 33.27,27.05 27.81,32.51 IC3.5
N$9
  Top 0.203: Q2.1 58.42,7.37 57.66,7.37 R15.2 56.64,6.86 56.64,6.73 55.24,6.73 Q1.3
N$10  (via drill 0.51)
  Top 0.203: R6.1 13.34,40.26 13.34,39.5 R3.2 12.83,38.35 v12.06,38.35 | R1.2 9.14,23.5 9.14,22.35 J1.CONDUCTOR
  Bottom 0.203: v12.06,38.35 12.06,29.21 9.14,26.29 9.14,22.35 J1.CONDUCTOR
N$11
  Top 0.203: R14.1 52.7,10.03 52.7,7.75 Q1.1
N$12
  Top 0.203: R18.2 59.05,10.92 59.94,10.92 59.94,12.19 60.33,12.19 C11.2 61.59,12.83 61.59,13.59 63.37,15.37 70.87,15.37 72.52,17.02 72.52,18.92 75.18,21.59 SW1.C2
N$13  (via drill 0.51)
  Top 0.203: R18.1 57.78,12.45 56.52,12.45 R20.2 v55.88,17.27
  Bottom 0.203: v55.88,17.27 D2.A
N$14  (via drill 0.51)
  Top 0.203: v61.85,7.62 61.85,6.73 Q2.3
  Bottom 0.203: v61.85,7.62 67.18,7.62 69.72,10.16 70.99,10.16 72.14,11.43 76.71,16 77.98,16 78.99,17.02 SW1.NC2
N$15
  Top 0.203: C11.1 61.59,10.54 62.87,10.54 R21.2 63.88,10.03 63.88,7.75 Q3.1
N$16
  Top 0.203: AUDIO-.TP 68.83,7.62 67.56,6.35 Q3.3 65.91,6.35
N$17
  Top 0.203: D1.1A 33.27,5.59 34.92,5.59 C1.2 36.2,5.46 36.96,5.46 37.34,5.08 38.23,5.08 IC1.1
N$18
  Top 0.203: C4.2 41.78,34.42 IC2.2
N$19
  Top 0.203: +28V.TP F1.1A
N$20
  Top 0.203: D1.2K 29.08,8.64 F1.2A
N$21  (via drill 0.51)
  Top 0.203: C5.2 70.99,23.75 70.99,22.73 R9.2 70.48,22.35 69.09,22.35 R10.W 65.66,22.1 65.66,19.81 R10.CW | R11.1 18.92,37.59 18.92,36.58 IC3.1 20.57,36.2 21.34,36.2 22.1,35.43 22.1,34.16 v21.97,34.04
  Bottom 0.203: v21.97,34.04 29.46,34.04 31.62,36.2 35.56,36.2 50.42,21.34 58.8,21.34 62.1,18.03 62.99,18.03 R10.CW
N$22  (via drill 0.51)
  Top 0.203: 17.27,40.89 R6.2 14.99,41.53 14.99,42.29 14.86,42.42 11.81,42.42 11.18,41.78 11.18,41.02 J3.1 | 17.27,40.89 R7.1 | 17.27,40.89 17.27,35.31 18.54,35.31 IC3.2 v21.34,35.05 | C5.1 72.9,23.75 72.9,22.73 R9.1 72.83,21.53 69.85,18.54 R10.CCW
  Bottom 0.203: v21.34,35.05 24.13,35.05 26.67,37.59 49.02,37.59 67.44,19.18 68.33,19.18 R10.CCW
N$23
  Top 0.203: R4.2 12.83,37.21 10.92,37.21 J3.2
N$24
  Top 0.203: R17.1 91.69,23.11 93.47,23.11 R16.W
N$25
  Top 0.203: R8.2 17.4,33.78 IC3.3
N$26
  Top 0.203: C4.1 41.78,36.96 IC2.4
N$27  (via drill 0.51)
  Top 0.203: v16.51,36.45 15.62,36.45 R4.1 | v23.62,29.34 24.51,29.34 26.23,27.62 | 26.23,27.62 26.29,27.56 26.29,26.8 R2.2 | C2.2 31.11,26.8 31.11,27.56 30.99,27.69 26.29,27.69 26.23,27.62
  Bottom 0.203: v16.51,36.45 v23.62,29.34
N$28
  Top 0.203: R22.2 148.84,23.5 148.84,22.35 J7.CONDUCTOR
N$29
  Top 0.203: R3.1 14.73,38.23 14.1,38.23 14.1,35.43 13.84,35.18 J3.3
N$30  (via drill 0.51)
  Top 0.203: 130.56,35.05 130.56,34.54 152.27,12.83 156.84,12.83 R29.2 157.86,12.83 v157.86,13.59 | IC5.7 130.56,35.05 | v131.19,36.83 131.19,38.35 C13.2 | 130.56,35.05 v130.56,35.18
  Bottom 0.203: v131.19,36.83 131.19,35.81 v130.56,35.18 | v157.86,13.59 175.01,13.59 180.47,19.05 184.78,19.05 185.55,18.29 186.44,18.29 SW2.NC1
N$31
  Top 0.203: IC5.6 127,33.78 126.87,33.91 126.87,35.43 125.48,36.83 125.48,37.59 125.22,37.59 R24.2 124.33,38.61 123.83,38.61 123.83,42.29 123.95,42.42 126.11,42.42 126.36,42.16 126.36,41.4 R23.1
N$32
  Top 0.203: R23.2 130.68,40.77 C13.1
N$33
  Top 0.203: R22.1 151.26,24.77 169.29,24.77 170.43,25.91 179.45,25.91 181.61,23.75 184.78,23.75 185.67,22.86 186.44,22.86 SW2.C1
N$34
  Top 0.203: R35.2 193.04,23.5 191.64,23.5 189.99,25.15 189.23,25.15 SW2.NO1
N$35
  Top 0.203: R26.1 131.06,24 131.06,22.35 J6.CONDUCTOR
N$36
  Top 0.203: R27.2 133.99,25.91 134.87,25.91 134.87,25.53 137.29,25.53 137.41,25.65 137.41,27.05 131.95,32.51 IC5.5
N$37  (via drill 0.51)
  Top 0.203: R34.1 117.47,40.26 117.47,39.5 R38.2 116.97,38.35 v116.2,38.35 | R28.2 113.28,23.5 113.28,22.35 J5.CONDUCTOR
  Bottom 0.203: v116.2,38.35 116.2,29.21 113.28,26.29 113.28,22.35 J5.CONDUCTOR
N$38
  Top 0.203: Q5.1 162.56,7.37 161.8,7.37 R30.2 160.78,6.86 160.78,6.73 159.38,6.73 Q4.3
N$39
  Top 0.203: R29.1 156.84,10.03 156.84,7.75 Q4.1
N$40
  Top 0.203: R31.2 163.19,10.92 164.08,10.92 164.08,12.19 164.47,12.19 C14.2 165.74,12.83 165.74,13.59 167.51,15.37 175.01,15.37 176.66,17.02 176.66,18.92 179.32,21.59 SW2.C2
N$41  (via drill 0.51)
  Top 0.203: R31.1 161.93,12.45 160.66,12.45 R36.2 v160.02,17.27
  Bottom 0.203: v160.02,17.27 D3.A
N$42
  Top 0.203: C14.1 165.74,10.54 167,10.54 R32.2 168.02,10.03 168.02,7.75 Q6.1
N$43
  Top 0.203: D4.1A 137.41,5.59 139.06,5.59 C16.2 140.34,5.46 141.1,5.46 141.48,5.08 142.37,5.08 IC4.1
N$44
  Top 0.203: D4.2K 133.22,8.64 F2.2A
N$45
  Top 0.203: +28V1.TP F2.1A
N$46
  Top 0.203: R35.1 195.83,23.11 197.61,23.11 R25.W
N$47  (via drill 0.51)
  Top 0.203: v165.99,7.62 165.99,6.73 Q5.3
  Bottom 0.203: v165.99,7.62 171.32,7.62 173.86,10.16 175.13,10.16 176.28,11.43 180.85,16 182.12,16 183.13,17.02 SW2.NC2
N$48
  Top 0.203: AUDIO-1.TP 172.97,7.62 171.7,6.35 Q6.3 170.05,6.35
N$49
  Top 0.203: C18.2 145.92,34.42 IC6.2
N$50
  Top 0.203: C18.1 145.92,36.96 IC6.4
N$51  (via drill 0.51)
  Top 0.203: v120.65,36.45 119.76,36.45 R40.1 | v127.76,29.34 128.65,29.34 130.37,27.62 | 130.37,27.62 130.43,27.56 130.43,26.8 R26.2 | C15.2 135.25,26.8 135.25,27.56 135.13,27.69 130.43,27.69 130.37,27.62
  Bottom 0.203: v120.65,36.45 v127.76,29.34
N$52  (via drill 0.51)
  Top 0.203: C22.2 175.13,23.75 175.13,22.73 R41.2 174.62,22.35 173.23,22.35 R37.W 169.8,22.1 169.8,19.81 R37.CW | R24.1 123.06,37.59 123.06,36.58 IC5.1 124.71,36.2 125.48,36.2 126.24,35.43 126.24,34.16 v126.11,34.04
  Bottom 0.203: v126.11,34.04 133.6,34.04 135.76,36.2 139.7,36.2 154.56,21.34 162.94,21.34 166.24,18.03 167.13,18.03 R37.CW
N$53  (via drill 0.51)
  Top 0.203: 121.41,40.89 R34.2 119.13,41.53 119.13,42.29 119,42.42 115.95,42.42 115.32,41.78 115.32,41.02 J8.1 | 121.41,40.89 R39.1 | 121.41,40.89 121.41,35.31 122.68,35.31 IC5.2 v125.48,35.05 | C22.1 177.04,23.75 177.04,22.73 R41.1 176.97,21.53 173.99,18.54 R37.CCW
  Bottom 0.203: v125.48,35.05 128.27,35.05 130.81,37.59 153.16,37.59 171.58,19.18 172.47,19.18 R37.CCW
N$54
  Top 0.203: R40.2 116.97,37.21 115.06,37.21 J8.2
N$55
  Top 0.203: R38.1 118.87,38.23 118.24,38.23 118.24,35.43 117.98,35.18 J8.3
N$56
  Top 0.203: R42.2 121.54,33.78 IC5.3
N$57
  Top 0.203: R43.2 44.7,70.48 44.7,69.34 J11.CONDUCTOR
N$58  (via drill 0.51)
  Top 0.203: 26.42,82.04 26.42,81.53 48.13,59.82 52.7,59.82 R50.2 53.72,59.82 v53.72,60.58 | IC8.7 26.42,82.04 | v27.05,83.82 27.05,85.34 C24.2 | 26.42,82.04 v26.42,82.17
  Bottom 0.203: v27.05,83.82 27.05,82.8 v26.42,82.17 | v53.72,60.58 70.87,60.58 76.33,66.04 80.64,66.04 81.41,65.28 82.3,65.28 SW3.NC1
N$59
  Top 0.203: IC8.6 22.86,80.77 22.73,80.9 22.73,82.42 21.34,83.82 21.34,84.58 21.08,84.58 R45.2 20.19,85.6 19.68,85.6 19.68,89.28 19.81,89.41 21.97,89.41 22.23,89.15 22.23,88.39 R44.1
N$60
  Top 0.203: R44.2 26.54,87.76 C24.1
N$61
  Top 0.203: R43.1 47.12,71.75 65.15,71.75 66.29,72.9 75.31,72.9 77.47,70.74 80.64,70.74 81.53,69.85 82.3,69.85 SW3.C1
N$62
  Top 0.203: R56.2 88.9,70.48 87.5,70.48 85.85,72.14 85.09,72.14 SW3.NO1
N$63
  Top 0.203: R47.1 26.92,70.99 26.92,69.34 J10.CONDUCTOR
N$64
  Top 0.203: R48.2 29.84,72.9 30.73,72.9 30.73,72.52 33.15,72.52 33.27,72.64 33.27,74.04 27.81,79.5 IC8.5
N$65  (via drill 0.51)
  Top 0.203: R55.1 13.34,87.25 13.34,86.49 R59.2 12.83,85.34 v12.06,85.34 | R49.2 9.14,70.48 9.14,69.34 J9.CONDUCTOR
  Bottom 0.203: v12.06,85.34 12.06,76.2 9.14,73.28 9.14,69.34 J9.CONDUCTOR
N$66
  Top 0.203: Q8.1 58.42,54.36 57.66,54.36 R51.2 56.64,53.85 56.64,53.72 55.24,53.72 Q7.3
N$67
  Top 0.203: R50.1 52.7,57.02 52.7,54.74 Q7.1
N$68
  Top 0.203: R52.2 59.05,57.91 59.94,57.91 59.94,59.18 60.33,59.18 C25.2 61.59,59.82 61.59,60.58 63.37,62.36 70.87,62.36 72.52,64.01 72.52,65.91 75.18,68.58 SW3.C2
N$69  (via drill 0.51)
  Top 0.203: R52.1 57.78,59.44 56.52,59.44 R57.2 v55.88,64.26
  Bottom 0.203: v55.88,64.26 D5.A
N$70
  Top 0.203: C25.1 61.59,57.53 62.87,57.53 R53.2 63.88,57.02 63.88,54.74 Q9.1
N$71
  Top 0.203: D6.1A 33.27,52.58 34.92,52.58 C27.2 36.2,52.45 36.96,52.45 37.34,52.07 38.23,52.07 IC7.1
N$72
  Top 0.203: D6.2K 29.08,55.63 F3.2A
N$73
  Top 0.203: +28V2.TP F3.1A
N$74
  Top 0.203: R56.1 91.69,70.1 93.47,70.1 R46.W
N$75  (via drill 0.51)
  Top 0.203: v61.85,54.61 61.85,53.72 Q8.3
  Bottom 0.203: v61.85,54.61 67.18,54.61 69.72,57.15 70.99,57.15 72.14,58.42 76.71,62.99 77.98,62.99 78.99,64.01 SW3.NC2
N$76
  Top 0.203: AUDIO-2.TP 68.83,54.61 67.56,53.34 Q9.3 65.91,53.34
N$77
  Top 0.203: C29.2 41.78,81.41 IC9.2
N$78
  Top 0.203: C29.1 41.78,83.95 IC9.4
N$79  (via drill 0.51)
  Top 0.203: v16.51,83.44 15.62,83.44 R61.1 | v23.62,76.33 24.51,76.33 26.23,74.61 | 26.23,74.61 26.29,74.55 26.29,73.79 R47.2 | C26.2 31.11,73.79 31.11,74.55 30.99,74.68 26.29,74.68 26.23,74.61
  Bottom 0.203: v16.51,83.44 v23.62,76.33
N$80  (via drill 0.51)
  Top 0.203: C33.2 70.99,70.74 70.99,69.72 R62.2 70.48,69.34 69.09,69.34 R58.W 65.66,69.09 65.66,66.8 R58.CW | R45.1 18.92,84.58 18.92,83.57 IC8.1 20.57,83.19 21.34,83.19 22.1,82.42 22.1,81.15 v21.97,81.03
  Bottom 0.203: v21.97,81.03 29.46,81.03 31.62,83.19 35.56,83.19 50.42,68.33 58.8,68.33 62.1,65.02 62.99,65.02 R58.CW
N$81  (via drill 0.51)
  Top 0.203: 17.27,87.88 R55.2 14.99,88.52 14.99,89.28 14.86,89.41 11.81,89.41 11.18,88.77 11.18,88.01 J12.1 | 17.27,87.88 R60.1 | 17.27,87.88 17.27,82.3 18.54,82.3 IC8.2 v21.34,82.04 | C33.1 72.9,70.74 72.9,69.72 R62.1 72.83,68.52 69.85,65.53 R58.CCW
  Bottom 0.203: v21.34,82.04 24.13,82.04 26.67,84.58 49.02,84.58 67.44,66.17 68.33,66.17 R58.CCW
N$82
  Top 0.203: R61.2 12.83,84.2 10.92,84.2 J12.2
N$83
  Top 0.203: R59.1 14.73,85.22 14.1,85.22 14.1,82.42 13.84,82.17 J12.3
N$84
  Top 0.203: R63.2 17.4,80.77 IC8.3
N$85
  Top 0.203: R64.2 148.84,70.48 148.84,69.34 J15.CONDUCTOR
N$86  (via drill 0.51)
  Top 0.203: 130.56,82.04 130.56,81.53 152.27,59.82 156.84,59.82 R71.2 157.86,59.82 v157.86,60.58 | IC11.7 130.56,82.04 | v131.19,83.82 131.19,85.34 C35.2 | 130.56,82.04 v130.56,82.17
  Bottom 0.203: v131.19,83.82 131.19,82.8 v130.56,82.17 | v157.86,60.58 175.01,60.58 180.47,66.04 184.78,66.04 185.55,65.28 186.44,65.28 SW4.NC1
N$87
  Top 0.203: IC11.6 127,80.77 126.87,80.9 126.87,82.42 125.48,83.82 125.48,84.58 125.22,84.58 R66.2 124.33,85.6 123.83,85.6 123.83,89.28 123.95,89.41 126.11,89.41 126.36,89.15 126.36,88.39 R65.1
N$88
  Top 0.203: R65.2 130.68,87.76 C35.1
N$89
  Top 0.203: R64.1 151.26,71.75 169.29,71.75 170.43,72.9 179.45,72.9 181.61,70.74 184.78,70.74 185.67,69.85 186.44,69.85 SW4.C1
N$90
  Top 0.203: R77.2 193.04,70.48 191.64,70.48 189.99,72.14 189.23,72.14 SW4.NO1
N$91
  Top 0.203: R68.1 131.06,70.99 131.06,69.34 J14.CONDUCTOR
N$92
  Top 0.203: R69.2 133.99,72.9 134.87,72.9 134.87,72.52 137.29,72.52 137.41,72.64 137.41,74.04 131.95,79.5 IC11.5
N$93  (via drill 0.51)
  Top 0.203: R76.1 117.47,87.25 117.47,86.49 R80.2 116.97,85.34 v116.2,85.34 | R70.2 113.28,70.48 113.28,69.34 J13.CONDUCTOR
  Bottom 0.203: v116.2,85.34 116.2,76.2 113.28,73.28 113.28,69.34 J13.CONDUCTOR
N$94
  Top 0.203: Q11.1 162.56,54.36 161.8,54.36 R72.2 160.78,53.85 160.78,53.72 159.38,53.72 Q10.3
N$95
  Top 0.203: R71.1 156.84,57.02 156.84,54.74 Q10.1
N$96
  Top 0.203: R73.2 163.19,57.91 164.08,57.91 164.08,59.18 164.47,59.18 C36.2 165.74,59.82 165.74,60.58 167.51,62.36 175.01,62.36 176.66,64.01 176.66,65.91 179.32,68.58 SW4.C2
N$97  (via drill 0.51)
  Top 0.203: R73.1 161.93,59.44 160.66,59.44 R78.2 v160.02,64.26
  Bottom 0.203: v160.02,64.26 D7.A
N$98
  Top 0.203: C36.1 165.74,57.53 167,57.53 R74.2 168.02,57.02 168.02,54.74 Q12.1
N$99
  Top 0.203: D8.1A 137.41,52.58 139.06,52.58 C38.2 140.34,52.45 141.1,52.45 141.48,52.07 142.37,52.07 IC10.1
N$100
  Top 0.203: D8.2K 133.22,55.63 F4.2A
N$101
  Top 0.203: +28V3.TP F4.1A
N$102
  Top 0.203: R77.1 195.83,70.1 197.61,70.1 R67.W
N$103  (via drill 0.51)
  Top 0.203: v165.99,54.61 165.99,53.72 Q11.3
  Bottom 0.203: v165.99,54.61 171.32,54.61 173.86,57.15 175.13,57.15 176.28,58.42 180.85,62.99 182.12,62.99 183.13,64.01 SW4.NC2
N$104
  Top 0.203: AUDIO-3.TP 172.97,54.61 171.7,53.34 Q12.3 170.05,53.34
N$105
  Top 0.203: C40.2 145.92,81.41 IC12.2
N$106
  Top 0.203: C40.1 145.92,83.95 IC12.4
N$107  (via drill 0.51)
  Top 0.203: v120.65,83.44 119.76,83.44 R82.1 | v127.76,76.33 128.65,76.33 130.37,74.61 | 130.37,74.61 130.43,74.55 130.43,73.79 R68.2 | C37.2 135.25,73.79 135.25,74.55 135.13,74.68 130.43,74.68 130.37,74.61
  Bottom 0.203: v120.65,83.44 v127.76,76.33
N$108  (via drill 0.51)
  Top 0.203: C44.2 175.13,70.74 175.13,69.72 R83.2 174.62,69.34 173.23,69.34 R79.W 169.8,69.09 169.8,66.8 R79.CW | R66.1 123.06,84.58 123.06,83.57 IC11.1 124.71,83.19 125.48,83.19 126.24,82.42 126.24,81.15 v126.11,81.03
  Bottom 0.203: v126.11,81.03 133.6,81.03 135.76,83.19 139.7,83.19 154.56,68.33 162.94,68.33 166.24,65.02 167.13,65.02 R79.CW
N$109  (via drill 0.51)
  Top 0.203: 121.41,87.88 R76.2 119.13,88.52 119.13,89.28 119,89.41 115.95,89.41 115.32,88.77 115.32,88.01 J16.1 | 121.41,87.88 R81.1 | 121.41,87.88 121.41,82.3 122.68,82.3 IC11.2 v125.48,82.04 | C44.1 177.04,70.74 177.04,69.72 R83.1 176.97,68.52 173.99,65.53 R79.CCW
  Bottom 0.203: v125.48,82.04 128.27,82.04 130.81,84.58 153.16,84.58 171.58,66.17 172.47,66.17 R79.CCW
N$110
  Top 0.203: R82.2 116.97,84.2 115.06,84.2 J16.2
N$111
  Top 0.203: R80.1 118.87,85.22 118.24,85.22 118.24,82.42 117.98,82.17 J16.3
N$112
  Top 0.203: R84.2 121.54,80.77 IC11.3

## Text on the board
Top: ALPS - AOM Laser Power Stabilization | ALPS - AOM Laser Power Stabilization | Amp | Amp | University of Toronto - Physics | University of Toronto - Physics | PD | PD | J.Thywissen Labs | J.Thywissen Labs | Rev: B1 | Rev: B1 | - | - | Aud | Aud | 0.25A | + | 0.25A | + | ALPS - AOM Laser Power Stabilization | ALPS - AOM Laser Power Stabilization | Amp | Amp | University of Toronto - Physics | University of Toronto - Physics | PD | PD | J.Thywissen Labs | J.Thywissen Labs | Rev: B1 | Rev: B1 | - | - | Aud | Aud | 0.25A | + | 0.25A | +
Document: A. Stummer July'08 | B1 | 0.2mm(0.008") | 0.2mm(0.008") | 0.2mm(0.008") | 0.125mm(0.005") | 0.125mm(0.005") | Following are misc parts: | B1 July'08 A.Stummer Redesign. | A2 July'08 A.Stummer As assembled on Rev:A1 PCB. | A1 June'08 A.Stummer Initial design on Rev:A1 PCB.
Text: ALPS - AOM Laser | Power Stabilization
